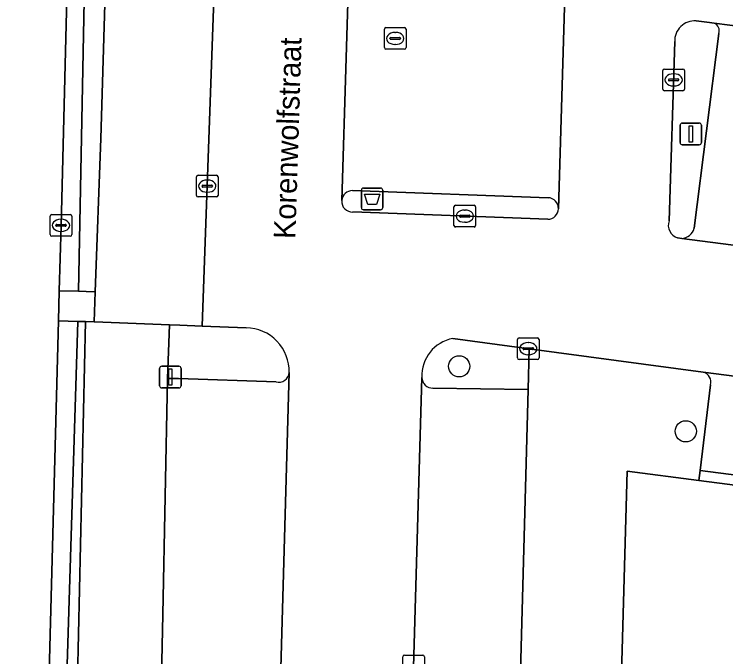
# Model space of a CAD drawing. Extents: x 160023 to 161302, y 384750 to 385707.
# Drawn here: x 160645.83 to 160678.68, y 384949.81 to 384979.46 of the extents above; entities that cross this region are included whole.
import ezdxf

# ---------------------------------------------------------------- set-up
doc = ezdxf.new("R2010")
doc.units = 0
for name, color, linetype in [('IMGEO_Afvalbak', 7, 'Continuous'), ('IMGEO_Boom', 7, 'Continuous'), ('IMGEO_Erf', 7, 'Continuous'), ('IMGEO_Groenvoorziening', 7, 'Continuous'), ('IMGEO_Haag', 7, 'Continuous'), ('IMGEO_Hek', 7, 'Continuous'), ('IMGEO_Kolk', 7, 'Continuous'), ('IMGEO_Lichtmast', 7, 'Continuous'), ('IMGEO_Openbare_ruimte_label', 7, 'Continuous'), ('IMGEO_Parkeervlak_open', 7, 'Continuous'), ('IMGEO_Rijbaan_lokaal_open', 7, 'Continuous'), ('IMGEO_Rioolput', 7, 'Continuous'), ('IMGEO_Verkeerseiland_open', 7, 'Continuous'), ('IMGEO_Voetpad_open', 7, 'Continuous')]:
    doc.layers.add(name, color=color, linetype=linetype)

msp = doc.modelspace()

# ---------------------------------------------------------------- linework, layer by layer
at = {"layer": 'IMGEO_Afvalbak'}
for p, q in [((160661.856, 384970.535), (160661.856, 384971.335)), ((160661.856, 384971.335), (160661.856, 384970.535)), ((160661.956, 384971.435), (160662.746, 384971.435)), ((160662.746, 384971.435), (160661.956, 384971.435)), ((160662.846, 384971.335), (160662.846, 384970.535)), ((160662.846, 384970.535), (160662.846, 384971.335)), ((160662.746, 384970.435), (160661.956, 384970.435)), ((160661.956, 384970.435), (160662.746, 384970.435))]:
    msp.add_line(p, q, dxfattribs=at)
msp.add_lwpolyline([(160661.999, 384971.149), (160662.703, 384971.149), (160662.554, 384970.679), (160662.148, 384970.679), (160661.999, 384971.149)], dxfattribs=at)
for centre, start, end in [((160661.956, 384971.335), 90, 180), ((160661.956, 384971.335), 90, 180), ((160662.746, 384971.335), 0, 90), ((160662.746, 384971.335), 360, 90), ((160661.956, 384970.535), 180, 270), ((160661.956, 384970.535), 180, 270), ((160662.746, 384970.535), 270, 0), ((160662.746, 384970.535), 270, 0)]:
    msp.add_arc(centre, 0.1, start, end, dxfattribs=at)
at = {"layer": 'IMGEO_Boom'}
for centre in [(160666.372, 384963.213), (160676.831, 384960.214)]:
    msp.add_circle(centre, 0.489, dxfattribs=at)
at = {"layer": 'IMGEO_Erf'}
for points in [[(160560.795, 385034.884), (160559.171, 385029.51), (160557.56, 385025.42), (160561.06, 385023.947), (160558.17, 385016.931), (160554.593, 385018.402), (160547.007, 385000), (160533.821, 384967.876), (160522.539, 384940.554), (160512.105, 384915.262), (160554.587, 384914.151), (160581.47, 384913.473), (160594.508, 384913.145), (160640.573, 384911.984), (160646.505, 384911.834), (160646.546, 384915.051), (160646.87, 384926.579), (160647.41, 384947.939), (160647.874, 384965.311), (160647.911, 384966.699), (160647.992, 384969.715)], [(160647.992, 384969.715), (160648.747, 385000), (160648.757, 385000.381), (160648.778, 385001.243), (160648.963, 385008.672), (160649.153, 385016.8), (160636.372, 385021.965), (160636.673, 385022.662), (160632.039, 385024.523), (160631.763, 385023.881), (160622.955, 385027.473), (160621.584, 385028.019), (160621.857, 385028.675), (160619.435, 385029.588), (160619.198, 385028.903), (160618.561, 385027.337), (160615.591, 385028.545)]]:
    msp.add_lwpolyline(points, dxfattribs=at)
msp.add_lwpolyline([(160720.402, 384952.382), (160715.365, 384953.034), (160677.436, 384957.941), (160674.12, 384958.37), (160672.758, 384909.466), (160672.719, 384908.083), (160714.697, 384906.942)], close=True, dxfattribs=at)
at = {"layer": 'IMGEO_Groenvoorziening'}
for points in [[(160649.432, 384999.007), (160649.475, 385001.225), (160648.778, 385001.243), (160648.757, 385000.381), (160648.747, 385000), (160647.992, 384969.715), (160647.911, 384966.699), (160648.803, 384966.675)], [(160650.553, 384998.013), (160651.244, 384997.984), (160651.312, 384998.953), (160650.027, 384998.994), (160649.432, 384999.007), (160648.803, 384966.675), (160649.155, 384966.666), (160649.573, 384966.654), (160649.825, 384973.719)], [(160648.776, 384965.287), (160647.874, 384965.311), (160647.41, 384947.939), (160646.87, 384926.579), (160646.546, 384915.051), (160646.505, 384911.834), (160647.109, 384911.819)], [(160649.118, 384965.278), (160648.776, 384965.287), (160647.109, 384911.819), (160646.946, 384908.708), (160647.918, 384908.668), (160648.008, 384914.647), (160648.053, 384917.632), (160648.264, 384927.083), (160648.657, 384944.671)], [(160652.902, 384962.653), (160652.997, 384965.13), (160649.928, 384965.247), (160649.523, 384965.263), (160649.118, 384965.278), (160648.657, 384944.671), (160651.321, 384944.569), (160650.757, 384926.928), (160648.264, 384927.083), (160648.053, 384917.632), (160651.036, 384917.586), (160650.99, 384914.601), (160650.919, 384909.988), (160651.786, 384909.973), (160652.38, 384937.328), (160652.698, 384951.762)], [(160677.498, 384958.406), (160677.436, 384957.941), (160715.365, 384953.034), (160715.436, 384953.53), (160712.16, 384953.938)]]:
    msp.add_lwpolyline(points, close=True, dxfattribs=at)
msp.add_lwpolyline([(160677.64, 384962.941), (160669.602, 384964.021), (160669.551, 384962.149), (160668.123, 384909.507), (160672.758, 384909.466), (160674.12, 384958.37), (160677.436, 384957.941), (160677.498, 384958.406), (160677.973, 384962.356)], dxfattribs=at)
msp.add_arc((160677.525, 384962.488), 0.467, 343.5893, 75.7104, dxfattribs=at)
at = {"layer": 'IMGEO_Haag'}
for points in [[(160649.475, 385001.225), (160648.778, 385001.243), (160648.757, 385000.381), (160648.747, 385000), (160647.992, 384969.715), (160647.911, 384966.699), (160648.803, 384966.675), (160649.432, 384999.007)], [(160648.776, 384965.287), (160647.874, 384965.311), (160647.41, 384947.939), (160646.87, 384926.579), (160646.546, 384915.051), (160646.505, 384911.834), (160647.109, 384911.819)], [(160677.498, 384958.406), (160677.436, 384957.941), (160715.365, 384953.034), (160715.436, 384953.53), (160712.16, 384953.938)]]:
    msp.add_lwpolyline(points, close=True, dxfattribs=at)
at = {"layer": 'IMGEO_Hek'}
for points in [[(160648.053, 384917.632), (160648.264, 384927.083), (160648.657, 384944.671), (160649.118, 384965.278)], [(160677.436, 384957.941), (160674.12, 384958.37), (160672.758, 384909.466)], [(160720.402, 384952.382), (160715.365, 384953.034), (160677.436, 384957.941)]]:
    msp.add_lwpolyline(points, dxfattribs=at)
at = {"layer": 'IMGEO_Kolk'}
for p, q in [((160675.77, 384976.002), (160675.77, 384976.854)), ((160675.845, 384976.928), (160676.697, 384976.928)), ((160676.771, 384976.854), (160676.771, 384976.002)), ((160676.258, 384976.708), (160676.283, 384976.708)), ((160676.029, 384976.422), (160676.029, 384976.434)), ((160676.467, 384976.385), (160676.069, 384976.385)), ((160676.072, 384976.471), (160676.47, 384976.471)), ((160676.513, 384976.434), (160676.513, 384976.422)), ((160676.697, 384975.928), (160675.845, 384975.928)), ((160676.281, 384976.148), (160676.256, 384976.148)), ((160654.242, 384971.1), (160654.242, 384971.952)), ((160654.317, 384972.026), (160655.169, 384972.026)), ((160655.243, 384971.952), (160655.243, 384971.1)), ((160654.73, 384971.806), (160654.755, 384971.806)), ((160654.501, 384971.52), (160654.501, 384971.532)), ((160654.939, 384971.483), (160654.541, 384971.483)), ((160654.544, 384971.569), (160654.942, 384971.569)), ((160654.985, 384971.532), (160654.985, 384971.52)), ((160655.169, 384971.026), (160654.317, 384971.026)), ((160654.753, 384971.246), (160654.728, 384971.246)), ((160666.205, 384970.64), (160667.057, 384970.64)), ((160666.13, 384969.714), (160666.13, 384970.566)), ((160666.618, 384970.42), (160666.643, 384970.42)), ((160667.131, 384970.566), (160667.131, 384969.714)), ((160647.491, 384969.289), (160647.491, 384970.141)), ((160647.566, 384970.215), (160648.418, 384970.215)), ((160647.979, 384969.995), (160648.004, 384969.995)), ((160648.492, 384970.141), (160648.492, 384969.289)), ((160666.389, 384970.134), (160666.389, 384970.146)), ((160666.827, 384970.097), (160666.429, 384970.097)), ((160666.432, 384970.183), (160666.83, 384970.183)), ((160666.873, 384970.146), (160666.873, 384970.134)), ((160647.75, 384969.709), (160647.75, 384969.721)), ((160648.188, 384969.672), (160647.79, 384969.672)), ((160647.793, 384969.758), (160648.191, 384969.758)), ((160648.234, 384969.721), (160648.234, 384969.709)), ((160667.057, 384969.64), (160666.205, 384969.64)), ((160666.641, 384969.86), (160666.616, 384969.86)), ((160648.002, 384969.435), (160647.977, 384969.435)), ((160648.418, 384969.215), (160647.566, 384969.215)), ((160669.061, 384963.599), (160669.061, 384964.451)), ((160669.136, 384964.525), (160669.988, 384964.525)), ((160670.062, 384964.451), (160670.062, 384963.599)), ((160669.363, 384964.068), (160669.761, 384964.068)), ((160669.549, 384964.305), (160669.574, 384964.305)), ((160669.32, 384964.019), (160669.32, 384964.031)), ((160669.758, 384963.982), (160669.36, 384963.982)), ((160669.572, 384963.745), (160669.547, 384963.745)), ((160669.804, 384964.031), (160669.804, 384964.019)), ((160669.988, 384963.525), (160669.136, 384963.525)), ((160663.767, 384948.961), (160663.767, 384949.813)), ((160663.842, 384949.887), (160664.694, 384949.887)), ((160664.768, 384949.813), (160664.768, 384948.961))]:
    msp.add_line(p, q, dxfattribs=at)
for points in [[(160675.77, 384976.002), (160675.77, 384976.854)], [(160675.845, 384976.928), (160676.697, 384976.928)], [(160676.771, 384976.854), (160676.771, 384976.002)], [(160676.697, 384975.928), (160675.845, 384975.928)], [(160654.242, 384971.1), (160654.242, 384971.952)], [(160654.317, 384972.026), (160655.169, 384972.026)], [(160655.243, 384971.952), (160655.243, 384971.1)], [(160655.169, 384971.026), (160654.317, 384971.026)], [(160666.205, 384970.64), (160667.057, 384970.64)], [(160666.13, 384969.714), (160666.13, 384970.566)], [(160667.131, 384970.566), (160667.131, 384969.714)], [(160647.491, 384969.289), (160647.491, 384970.141)], [(160647.566, 384970.215), (160648.418, 384970.215)], [(160648.492, 384970.141), (160648.492, 384969.289)], [(160667.057, 384969.64), (160666.205, 384969.64)], [(160648.418, 384969.215), (160647.566, 384969.215)], [(160669.061, 384963.599), (160669.061, 384964.451)], [(160669.136, 384964.525), (160669.988, 384964.525)], [(160670.062, 384964.451), (160670.062, 384963.599)], [(160669.988, 384963.525), (160669.136, 384963.525)], [(160663.767, 384948.961), (160663.767, 384949.813)], [(160663.842, 384949.887), (160664.694, 384949.887)], [(160664.768, 384949.813), (160664.768, 384948.961)]]:
    msp.add_lwpolyline(points, dxfattribs=at)
for centre, radius, start, end in [((160675.847, 384976.852), 0.0765, 91.552, 178.448), ((160675.847, 384976.852), 0.0765, 91.552, 178.448), ((160676.695, 384976.852), 0.0765, 1.552, 88.448), ((160676.695, 384976.852), 0.0765, 1.552, 88.448), ((160676.069, 384976.431), 0.0403, 85.8775, 175.7526), ((160676.066, 384976.421), 0.0366, 178.938, 274.7102), ((160676.47, 384976.428), 0.043, 264.8664, 352.4533), ((160676.474, 384976.433), 0.0386, 1.7309, 96.639), ((160675.847, 384976.004), 0.0765, 181.552, 268.448), ((160675.847, 384976.004), 0.0765, 181.552, 268.448), ((160676.695, 384976.004), 0.0765, 271.552, 358.448), ((160676.695, 384976.004), 0.0765, 271.552, 358.448), ((160654.319, 384971.95), 0.0765, 91.552, 178.448), ((160654.319, 384971.95), 0.0765, 91.552, 178.448), ((160655.167, 384971.95), 0.0765, 1.552, 88.448), ((160655.167, 384971.95), 0.0765, 1.552, 88.448), ((160654.541, 384971.529), 0.0403, 85.8775, 175.7526), ((160654.538, 384971.519), 0.0366, 178.938, 274.7102), ((160654.942, 384971.526), 0.043, 264.8664, 352.4533), ((160654.946, 384971.531), 0.0386, 1.7309, 96.639), ((160654.319, 384971.102), 0.0765, 181.552, 268.448), ((160654.319, 384971.102), 0.0765, 181.552, 268.448), ((160655.167, 384971.102), 0.0765, 271.552, 358.448), ((160655.167, 384971.102), 0.0765, 271.552, 358.448), ((160666.207, 384970.564), 0.0765, 91.552, 178.448), ((160666.207, 384970.564), 0.0765, 91.552, 178.448), ((160667.055, 384970.564), 0.0765, 1.552, 88.448), ((160667.055, 384970.564), 0.0765, 1.552, 88.448), ((160647.568, 384970.139), 0.0765, 91.552, 178.448), ((160647.568, 384970.139), 0.0765, 91.552, 178.448), ((160648.416, 384970.139), 0.0765, 1.552, 88.448), ((160648.416, 384970.139), 0.0765, 1.552, 88.448), ((160666.429, 384970.143), 0.0403, 85.8775, 175.7526), ((160666.426, 384970.133), 0.0366, 178.938, 274.7102), ((160666.83, 384970.14), 0.043, 264.8664, 352.4533), ((160666.834, 384970.145), 0.0386, 1.7309, 96.639), ((160647.79, 384969.718), 0.0403, 85.8775, 175.7526), ((160647.787, 384969.708), 0.0366, 178.938, 274.7102), ((160648.191, 384969.715), 0.043, 264.8664, 352.4533), ((160648.195, 384969.72), 0.0386, 1.7309, 96.639), ((160666.207, 384969.716), 0.0765, 181.552, 268.448), ((160666.207, 384969.716), 0.0765, 181.552, 268.448), ((160667.055, 384969.716), 0.0765, 271.552, 358.448), ((160667.055, 384969.716), 0.0765, 271.552, 358.448), ((160647.568, 384969.291), 0.0765, 181.552, 268.448), ((160647.568, 384969.291), 0.0765, 181.552, 268.448), ((160648.416, 384969.291), 0.0765, 271.552, 358.448), ((160648.416, 384969.291), 0.0765, 271.552, 358.448), ((160669.138, 384964.449), 0.0765, 91.552, 178.448), ((160669.138, 384964.449), 0.0765, 91.552, 178.448), ((160669.986, 384964.449), 0.0765, 1.552, 88.448), ((160669.986, 384964.449), 0.0765, 1.552, 88.448), ((160669.36, 384964.028), 0.0403, 85.8775, 175.7526), ((160669.765, 384964.03), 0.0386, 1.7309, 96.639), ((160669.357, 384964.018), 0.0366, 178.938, 274.7102), ((160669.761, 384964.025), 0.043, 264.8664, 352.4533), ((160669.138, 384963.601), 0.0765, 181.552, 268.448), ((160669.138, 384963.601), 0.0765, 181.552, 268.448), ((160669.986, 384963.601), 0.0765, 271.552, 358.448), ((160669.986, 384963.601), 0.0765, 271.552, 358.448), ((160663.844, 384949.811), 0.0765, 91.552, 178.448), ((160663.844, 384949.811), 0.0765, 91.552, 178.448), ((160664.692, 384949.811), 0.0765, 1.552, 88.448), ((160664.692, 384949.811), 0.0765, 1.552, 88.448)]:
    msp.add_arc(centre, radius, start, end, dxfattribs=at)
for centre, major_axis, ratio, start_param, end_param in [((160676.257, 384976.428), (-0.387, 0.002), 0.722429, 4.712389, 7.853982), ((160676.282, 384976.428), (-0.39, 0.002), 0.717154, 1.570796, 4.712389), ((160654.729, 384971.526), (-0.387, 0.002), 0.722429, 4.712389, 7.853982), ((160654.754, 384971.526), (-0.39, 0.002), 0.717154, 1.570796, 4.712389), ((160666.617, 384970.14), (-0.387, 0.002), 0.722429, 4.712389, 7.853982), ((160666.642, 384970.14), (-0.39, 0.002), 0.717154, 1.570796, 4.712389), ((160647.978, 384969.715), (-0.387, 0.002), 0.722429, 4.712389, 7.853982), ((160648.003, 384969.715), (-0.39, 0.002), 0.717154, 1.570796, 4.712389), ((160669.548, 384964.025), (-0.387, 0.002), 0.722429, 4.712389, 7.853982), ((160669.573, 384964.025), (-0.39, 0.002), 0.717154, 1.570796, 4.712389)]:
    msp.add_ellipse(centre, major_axis=major_axis, ratio=ratio, start_param=start_param, end_param=end_param, dxfattribs=at)
at = {"layer": 'IMGEO_Lichtmast'}
for p, q in [((160676.566, 384973.531), (160676.566, 384974.331)), ((160676.566, 384974.331), (160676.566, 384973.531)), ((160676.666, 384974.431), (160677.456, 384974.431)), ((160677.456, 384974.431), (160676.666, 384974.431)), ((160677.556, 384974.331), (160677.556, 384973.531)), ((160677.556, 384973.531), (160677.556, 384974.331)), ((160677.456, 384973.431), (160676.666, 384973.431)), ((160676.666, 384973.431), (160677.456, 384973.431)), ((160652.544, 384962.319), (160652.544, 384963.119)), ((160652.544, 384963.119), (160652.544, 384962.319)), ((160652.644, 384963.219), (160653.434, 384963.219)), ((160653.434, 384963.219), (160652.644, 384963.219)), ((160653.534, 384963.119), (160653.534, 384962.319)), ((160653.534, 384962.319), (160653.534, 384963.119)), ((160653.434, 384962.219), (160652.644, 384962.219)), ((160652.644, 384962.219), (160653.434, 384962.219))]:
    msp.add_line(p, q, dxfattribs=at)
for points in [[(160676.986, 384974.306), (160677.136, 384974.306), (160677.136, 384973.556), (160676.986, 384973.556), (160676.986, 384974.306)], [(160652.964, 384963.094), (160653.114, 384963.094), (160653.114, 384962.344), (160652.964, 384962.344), (160652.964, 384963.094)]]:
    msp.add_lwpolyline(points, dxfattribs=at)
for centre, start, end in [((160676.666, 384974.331), 90, 180), ((160676.666, 384974.331), 90, 180), ((160677.456, 384974.331), 0, 90), ((160677.456, 384974.331), 360, 90), ((160676.666, 384973.531), 180, 270), ((160676.666, 384973.531), 180, 270), ((160677.456, 384973.531), 270, 0), ((160677.456, 384973.531), 270, 0), ((160652.644, 384963.119), 90, 180), ((160652.644, 384963.119), 90, 180), ((160653.434, 384963.119), 0, 90), ((160653.434, 384963.119), 360, 90), ((160652.644, 384962.319), 180, 270), ((160652.644, 384962.319), 180, 270), ((160653.434, 384962.319), 270, 0), ((160653.434, 384962.319), 270, 0)]:
    msp.add_arc(centre, 0.1, start, end, dxfattribs=at)
at = {"layer": 'IMGEO_Parkeervlak_open'}
for points in [[(160655.163, 384997.822), (160651.244, 384997.984), (160650.553, 384998.013), (160649.825, 384973.719), (160649.573, 384966.654), (160649.523, 384965.263), (160649.928, 384965.247), (160652.997, 384965.13), (160653.484, 384965.111), (160654.515, 384965.071), (160655.69, 384998.272)], [(160661.76, 384997.212), (160660.95, 384970.857)], [(160670.956, 384970.485), (160671.745, 384996.873)], [(160713.571, 384974.525), (160678.143, 384979.047)], [(160678.363, 384978.57), (160677.214, 384969.582)], [(160661.452, 384971.318), (160670.48, 384970.992)], [(160676.645, 384969.117), (160712.231, 384964.508)], [(160657.919, 384962.501), (160653.417, 384962.653), (160652.902, 384962.653), (160652.698, 384951.762), (160652.38, 384937.328), (160651.786, 384909.973), (160651.985, 384909.97), (160656.516, 384909.828), (160656.841, 384909.72), (160657.017, 384909.425), (160658.521, 384962.92)], [(160677.973, 384962.356), (160677.498, 384958.406), (160712.16, 384953.938), (160712.584, 384957.951), (160712.739, 384958.255), (160713.057, 384958.376), (160677.64, 384962.941)], [(160664.65, 384962.702), (160663.109, 384909.238)], [(160663.624, 384909.635), (160668.123, 384909.507), (160669.551, 384962.149), (160665.159, 384962.207)]]:
    msp.add_lwpolyline(points, dxfattribs=at)
for centre, radius, start, end in [((160677.985, 384978.685), 0.395, 343.0661, 66.4537), ((160661.443, 384970.824), 0.494, 88.9771, 176.1471), ((160670.457, 384970.494), 0.499, 359.0079, 87.3795), ((160676.626, 384969.721), 0.605, 271.8476, 346.6654), ((160658.05, 384962.954), 0.472, 253.8423, 355.8346), ((160677.525, 384962.488), 0.467, 343.5893, 75.7104), ((160665.142, 384962.699), 0.492, 179.6222, 271.9755)]:
    msp.add_arc(centre, radius, start, end, dxfattribs=at)
at = {"layer": 'IMGEO_Rijbaan_lokaal_open'}
for points in [[(160655.69, 384998.272), (160654.515, 384965.071), (160656.535, 384964.993)], [(160660.95, 384970.857), (160661.76, 384997.212)], [(160671.745, 384996.873), (160670.956, 384970.485)], [(160677.308, 384979.145), (160677.923, 384979.075), (160678.143, 384979.047), (160713.571, 384974.525)], [(160676.058, 384969.925), (160676.319, 384978.192)], [(160670.463, 384969.995), (160661.458, 384970.332)], [(160712.231, 384964.508), (160676.645, 384969.117), (160676.455, 384969.142)], [(160666.077, 384964.494), (160669.602, 384964.021), (160677.64, 384962.941), (160713.057, 384958.376), (160718.86, 384957.636), (160721.002, 384957.362), (160721.708, 384963.287)], [(160658.521, 384962.92), (160657.017, 384909.425), (160656.966, 384908.384), (160663.084, 384908.293), (160663.109, 384909.238), (160664.65, 384962.702)]]:
    msp.add_lwpolyline(points, dxfattribs=at)
for centre, radius, start, end in [((160677.233, 384978.233), 0.915, 85.2817, 182.5943), ((160661.44, 384970.822), 0.491, 175.9582, 272.1561), ((160670.457, 384970.494), 0.499, 270.6407, 359.0096), ((160676.627, 384969.721), 0.604, 160.3058, 253.4664), ((160656.507, 384962.978), 2.015, 358.3458, 89.1985), ((160666.388, 384962.782), 1.74, 100.2988, 182.6394)]:
    msp.add_arc(centre, radius, start, end, dxfattribs=at)
at = {"layer": 'IMGEO_Rioolput'}
for p, q in [((160662.993, 384978.84), (160663.845, 384978.84)), ((160662.918, 384977.914), (160662.918, 384978.766)), ((160663.406, 384978.62), (160663.431, 384978.62)), ((160663.919, 384978.766), (160663.919, 384977.914)), ((160663.177, 384978.334), (160663.177, 384978.346)), ((160663.615, 384978.297), (160663.217, 384978.297)), ((160663.22, 384978.383), (160663.618, 384978.383)), ((160663.661, 384978.346), (160663.661, 384978.334)), ((160663.845, 384977.84), (160662.993, 384977.84)), ((160663.429, 384978.06), (160663.404, 384978.06))]:
    msp.add_line(p, q, dxfattribs=at)
for points in [[(160662.993, 384978.84), (160663.845, 384978.84)], [(160662.918, 384977.914), (160662.918, 384978.766)], [(160663.919, 384978.766), (160663.919, 384977.914)], [(160663.845, 384977.84), (160662.993, 384977.84)]]:
    msp.add_lwpolyline(points, dxfattribs=at)
for centre, radius, start, end in [((160662.995, 384978.764), 0.0765, 91.552, 178.448), ((160662.995, 384978.764), 0.0765, 91.552, 178.448), ((160663.843, 384978.764), 0.0765, 1.552, 88.448), ((160663.843, 384978.764), 0.0765, 1.552, 88.448), ((160663.217, 384978.343), 0.0403, 85.8775, 175.7526), ((160663.214, 384978.333), 0.0366, 178.938, 274.7102), ((160663.618, 384978.34), 0.043, 264.8664, 352.4533), ((160663.622, 384978.345), 0.0386, 1.7309, 96.639), ((160662.995, 384977.916), 0.0765, 181.552, 268.448), ((160662.995, 384977.916), 0.0765, 181.552, 268.448), ((160663.843, 384977.916), 0.0765, 271.552, 358.448), ((160663.843, 384977.916), 0.0765, 271.552, 358.448)]:
    msp.add_arc(centre, radius, start, end, dxfattribs=at)
for centre, major_axis, ratio, start_param, end_param in [((160663.405, 384978.34), (-0.387, 0.002), 0.722429, 4.712389, 7.853982), ((160663.43, 384978.34), (-0.39, 0.002), 0.717154, 1.570796, 4.712389)]:
    msp.add_ellipse(centre, major_axis=major_axis, ratio=ratio, start_param=start_param, end_param=end_param, dxfattribs=at)
at = {"layer": 'IMGEO_Verkeerseiland_open'}
for points in [[(160678.143, 384979.047), (160677.923, 384979.075), (160677.308, 384979.145)], [(160677.214, 384969.582), (160678.363, 384978.57)], [(160676.319, 384978.192), (160676.058, 384969.925)], [(160670.48, 384970.992), (160661.452, 384971.318)], [(160661.458, 384970.332), (160670.463, 384969.995)], [(160676.455, 384969.142), (160676.645, 384969.117)], [(160656.535, 384964.993), (160654.515, 384965.071), (160653.484, 384965.111), (160652.997, 384965.13), (160652.902, 384962.653), (160653.417, 384962.653), (160657.919, 384962.501)], [(160665.159, 384962.207), (160669.551, 384962.149), (160669.602, 384964.021), (160666.077, 384964.494)]]:
    msp.add_lwpolyline(points, dxfattribs=at)
for centre, radius, start, end in [((160677.233, 384978.233), 0.915, 85.2817, 182.5943), ((160677.985, 384978.685), 0.395, 343.0661, 66.4537), ((160661.443, 384970.824), 0.494, 88.9771, 176.1471), ((160670.457, 384970.494), 0.499, 359.0079, 87.3795), ((160661.44, 384970.822), 0.491, 175.9582, 272.1561), ((160670.457, 384970.494), 0.499, 270.6407, 359.0096), ((160676.627, 384969.721), 0.604, 160.3058, 253.4664), ((160676.626, 384969.721), 0.605, 271.8476, 346.6654), ((160656.507, 384962.978), 2.015, 358.3458, 89.1985), ((160666.388, 384962.782), 1.74, 100.2988, 182.6394), ((160658.05, 384962.954), 0.472, 253.8423, 355.8346), ((160665.142, 384962.699), 0.492, 179.6222, 271.9755)]:
    msp.add_arc(centre, radius, start, end, dxfattribs=at)
at = {"layer": 'IMGEO_Voetpad_open'}
msp.add_lwpolyline([(160649.573, 384966.654), (160649.155, 384966.666), (160648.803, 384966.675), (160647.911, 384966.699), (160647.874, 384965.311), (160648.776, 384965.287), (160649.118, 384965.278), (160649.523, 384965.263)], close=True, dxfattribs=at)

# ---------------------------------------------------------------- texts
at = {"layer": 'IMGEO_Openbare_ruimte_label'}
msp.add_text('Korenwolfstraat', height=1, rotation=88.2244, dxfattribs=at).set_placement((160658.809, 384969.077))

doc.saveas('drawing.dxf')
